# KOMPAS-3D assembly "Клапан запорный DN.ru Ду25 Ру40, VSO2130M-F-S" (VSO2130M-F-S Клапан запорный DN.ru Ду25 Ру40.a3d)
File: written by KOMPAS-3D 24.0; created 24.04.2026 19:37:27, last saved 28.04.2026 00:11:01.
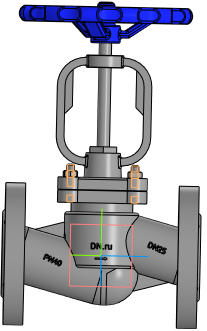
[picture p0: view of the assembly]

Document properties: Автор: DN.ru; Полное имя файла: C:\Работа\ГОТОВЫЕ ИСХОДНИКИ\VSO2130M-F-S Клапан запорный сальниковый DN.ru Ду15-100 Ру40\исходные материалы\DN25\VSO2130M-F-S Клапан запорный DN.ru Ду25 Ру40.a3d

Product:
- Component [detail]: Корпус  | qty 1  | pos. 1  | Масса: 6.9; Автор: R2D2; source file: Korpus.m3d
- Component [detail]: Деталь  | qty 1  | pos. 2  | Масса: 0.732425; Автор: mrdid; source file: rama.m3d
- Component [detail]: Деталь2  | qty 1  | pos. 3  | Масса: 0.594157; Автор: R2D2; additional columns: Типовые; source file: shturval.m3d
- Component [standard]: Шпилька М6-6gx25 ГОСТ 22032-76  | qty 4  | Масса: 0.005789; Раздел спецификации: Стандартные изделия; Рассекать на разрезах: no
- Component [standard]: Гайка М6-6H ГОСТ 5915-70  | qty 4  | Масса: 0.002573; Раздел спецификации: Стандартные изделия; Рассекать на разрезах: no
- Part/product: Клапан запорный DN.ru Ду25 Ру40  | designation VSO2130M-F-S
    Масса: 5.5
    Раздел спецификации: Прочие изделия
    Примечание: D090-01981

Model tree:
1. Контекстная связь:1  (with: Контекстная связь (Деталь):1)  (labels: Грань.Твердое тело1)
2. Контекстная связь:2  (with: Смещенная плоскость:4, Контекстная связь (Деталь):2)  (labels: Грань.Твердое тело1)
3. Контекстная связь:3  (with: Контекстная связь (Корпус):3)
4. Контекстная связь:4  (with: Эскиз:2, Ребро.Элемент выдавливания:14, Контекстная связь (Деталь):4)
5. Контекстная связь:5  (with: Контекстная связь (Деталь):5)
6. Массив по концентрической сетке:1  (with: Грань.Элемент выдавливания:1, Грань.Элемент выдавливания:15, Грань.Элемент выдавливания:3, Грань.Элемент выдавливания:2, Грань.Элемент выдавливания:16, Грань.Элемент выдавливания:14)  (labels: Грань.Твердое тело1)  (4 pattern instances)
     Шаг 2 = 360; Угол = 9

Referenced files in C:\Работа\ГОТОВЫЕ ИСХОДНИКИ\VSO2130M-F-S Клапан запорный сальниковый DN.ru Ду15-100 Ру40\исходные материалы\DN25\: Korpus.m3d, rama.m3d, shturval.m3d
Referenced files in C:\Program Files\ASCON\KOMPAS-3D v24\Libs\PolynomLib\DATA\vault\Methods\Kompas\3D\: PLib_Stud_1_900.m3d, PLib_Nut_OST92_900.m3d
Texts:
  BOSimple***PART:e489ae6d-d315-b2e9-dd59-4407119351be***SHORTLOC:Root±30±20±10±120±10±20[Нет;Без покрытия;Без указания материала;-;6;25;1;1]
  Крепежное изделие ГОСТ
  BOSimple***PART:832b7c99-94b5-75d7-382c-73b3a2f1c6df***SHORTLOC:Root±30±10±20±©{}110±10±50±60[Нет;Без покрытия;Без указания материала;-;6;1;10]
  Программные изделия  и базы данных
  VSO2130M-F-S
  Деталь2 Деталь2
  Шпилька М6-6gx25 ГОСТ 22032-76 (1)
  cut1
  Гайка М6-6H ГОСТ 5915-70 (1)
  bcut1
  hole1
  hcut1
  hole2
  Шпилька М6-6gx25 ГОСТ 22032-76 (2)
  Гайка М6-6H ГОСТ 5915-70 (2)
  Шпилька М6-6gx25 ГОСТ 22032-76 (3)
  Гайка М6-6H ГОСТ 5915-70 (3)
  Шпилька М6-6gx25 ГОСТ 22032-76 (4)
  Гайка М6-6H ГОСТ 5915-70 (4)
  Plane. Начало координат
  Плоскость ZX.Начало координат
  Плоскость XY.Начало координат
